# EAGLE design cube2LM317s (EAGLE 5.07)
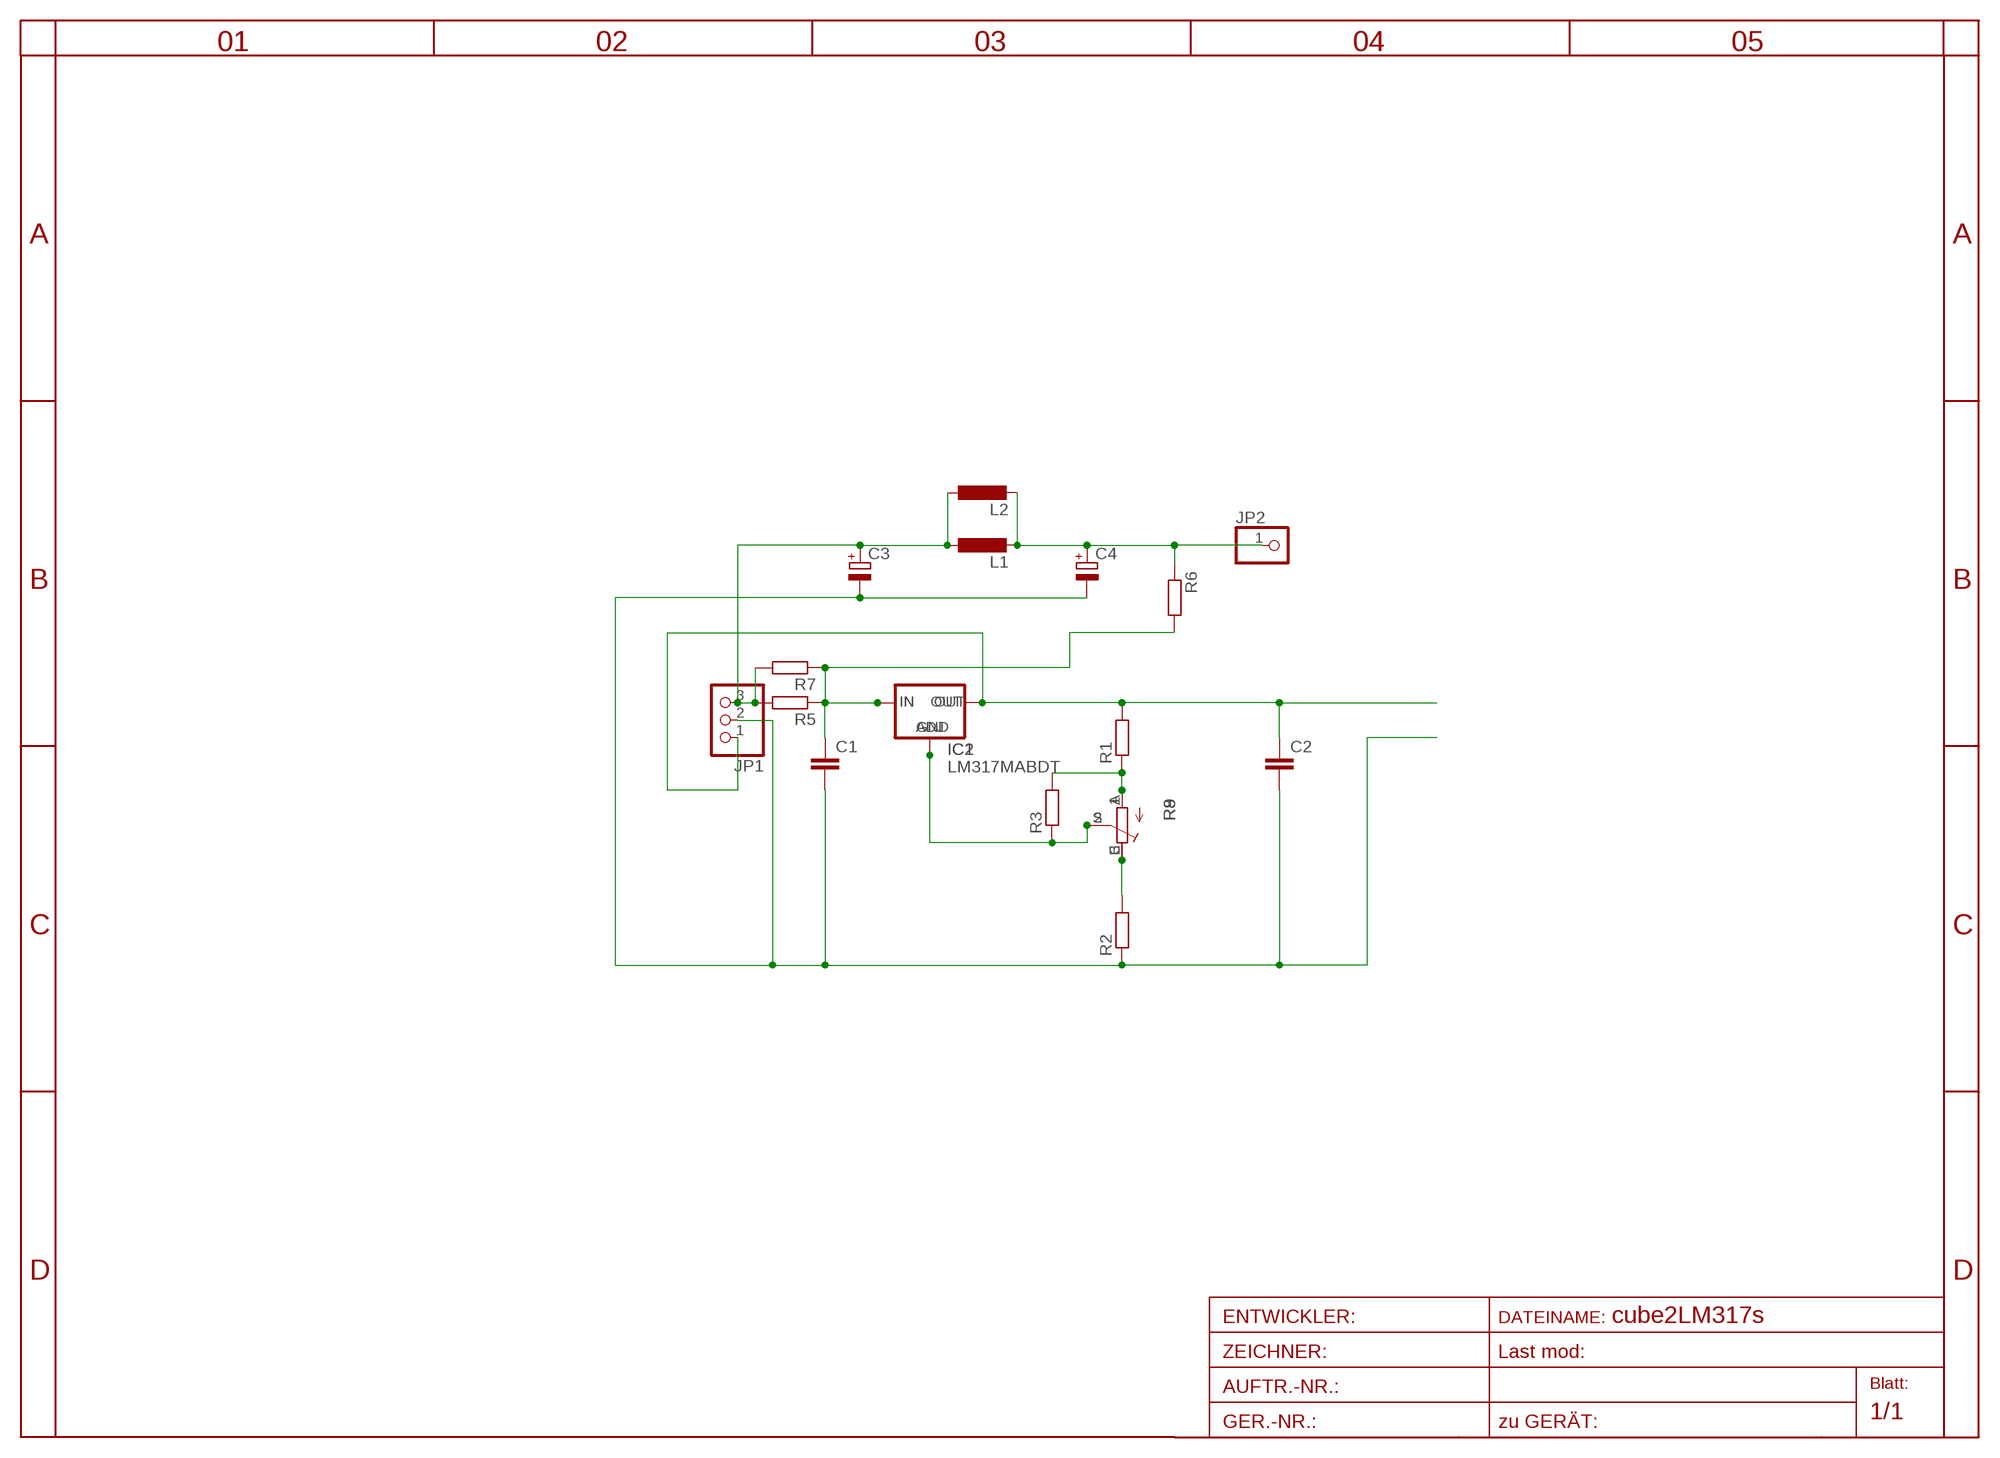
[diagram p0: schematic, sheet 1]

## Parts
C1  C-EUC1206  [C1206]
C2  C-EUC1206  [C1206]
C3  CPOL-EUE  [PANASONIC_E]
C4  CPOL-EUE  [PANASONIC_E]
IC1  LM317MABDT  [DPACK]
IC2  78XXS  [78XXS]
JP1  PINHD-1X3  [1X03]
JP2  PINHD-1X11X0.4  [1X01]
L1  L-EUPIS2816  [PIS2816]
L2  L-EUOPEN  [OPEN5]
R1  R-EU_R0805  [R0805]
R2  R-EU_R1206  [R1206]
R3  R-EU_R0805  [R0805]
R5  R-EU_R0805  [R0805]
R6  R-EU_R0805  [R0805]
R7  R-EU_R0805  [R0805]
R8  TRIM_EU-RAND160  [RANDL]
R9  R-TRIMM3214W  [RTRIM3214W]

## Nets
GND: C1.2 C2.2 C3.- C4.- JP1.2 R2.1
IN: C1.1 IC1.3(IN) IC2.IN R5.1 R6.2 R7.1
N$1: C3.+ JP1.3 L1.1 L2.1 R5.2 R7.2
N$3: C4.+ JP2.1 L1.2 L2.2 R6.1
N$4: IC1.1(ADJ) IC2.GND R3.1 R8.S R9.2(S)
N$6: R2.2 R8.E R9.3(A)
N$7: R1.1 R3.2 R8.A R9.1(E)
OUT: C2.1 IC1.4(OUT) IC2.OUT JP1.1 R1.2

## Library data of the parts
C1 C2 = rcl:C-EU: CAPACITOR, European symbol
C3 C4 = rcl:CPOL-EU: POLARIZED CAPACITOR, European symbol
IC1 = v-reg:LM317?*: 500 mA Adjustable Output Positive Voltage Regulator Source: http://www.onsemi.co.jp .. LM317M-D.PDF
IC2 = v-reg:78XXS: VOLTAGE REGULATOR
JP1 = pinhead:PINHD-1X3: PIN HEADER
JP2 = pinhead:PINHD-1X1: PIN HEADER
L1 L2 = rcl:L-EU: INDUCTOR, European symbol
R1-R3 R5-R7 = rcl:R-EU_: RESISTOR, European symbol
R8 = pot:TRIM_EU-: POTENTIOMETER
R9 = rcl:R-TRIMM: Trimm resistor

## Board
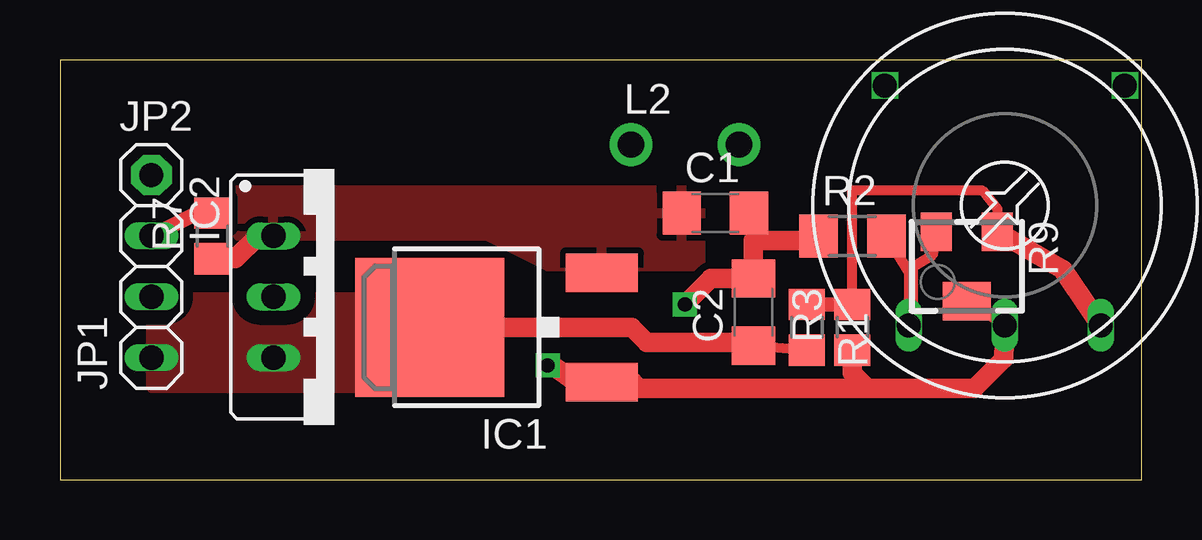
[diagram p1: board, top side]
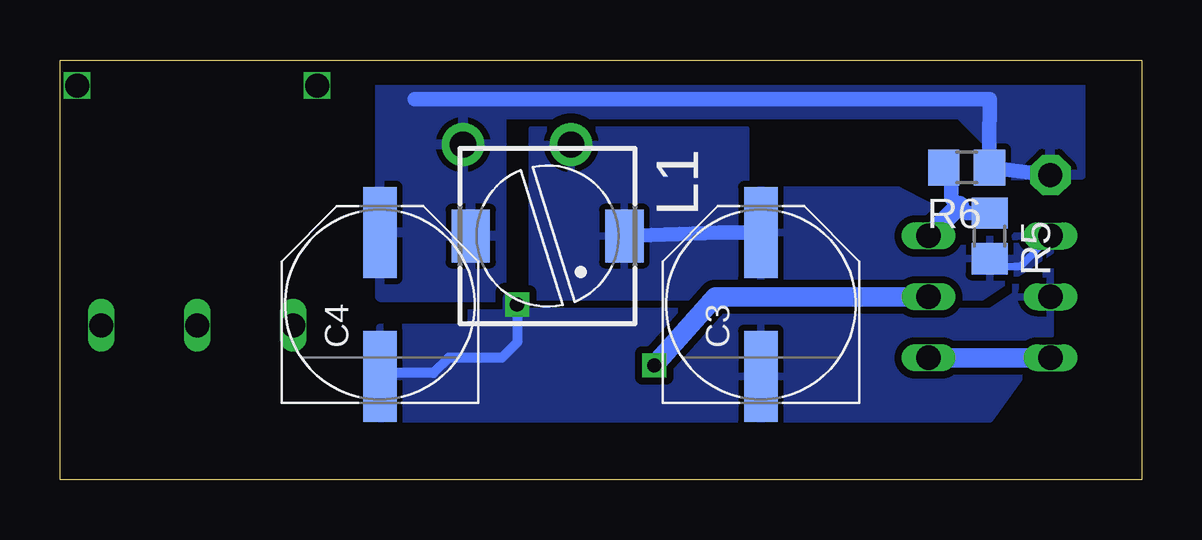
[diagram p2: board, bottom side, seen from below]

Size 45.08 x 17.5 mm. Coordinates in mm from the lower left corner, seen from the top.
Outline: 0,0 45.08,0 45.08,17.5 0,17.5 0,0
Copper layers (1*16): Top 0.035mm / dielectric 1.5mm / Bottom 0.035mm
Design rules "default": minimum track width 10mil, minimum drill 20mil, track to track 8mil, track to pad 8mil, pad to pad 8mil, via to via 8mil, smd to smd 8mil, copper to edge 40mil, drill to drill 8mil, minimum pad ring 1mil, minimum via ring 8mil, stop-mask expansion 4mil, vias tented up to drill 0mil, thermal gap 10mil

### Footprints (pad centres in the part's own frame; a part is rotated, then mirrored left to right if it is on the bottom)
C1206 = smd 1.6 x 1.8: 1 -1.4,0; 2 1.4,0
PANASONIC_E = smd 3.8 x 1.4: + 3,0; - -3,0
DPACK = smd 1.6 x 3: 1 -2.28,-4.8; 3 2.28,-4.8 | smd 5.8 x 6.2: 4 0,2.38
78XXS = drill 1.016 long: GND 0,-2.54; IN -2.54,-2.54; OUT 2.54,-2.54
1X03 = drill 1.016 long: 1 -2.54,0; 2 0,0; 3 2.54,0
1X01 = drill 1 pad 1.676 octagon: 1 0,0
PIS2816 = smd 2.2 x 1.6: 1 0,3.2; 2 0,-3.2
OPEN5 = drill 1.1 pad 1.778 round: 1 -2.25,0; 2 2.25,0
R0805 = smd 1.3 x 1.5: 1 -0.95,0; 2 0.95,0
R1206 = smd 1.6 x 1.803: 1 -1.422,0; 2 1.422,0
RANDL = drill 1 long: A -4,5; E 4,5; S 0,5 | drill 1 square: P$1 -5,-5; P$2 5,-5
RTRIM3214W = smd 1.3 x 1.6: 1 -1.275,-1.45; 3 1.275,-1.45 | smd 2 x 1.6: 2 0,1.45

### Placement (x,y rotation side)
C1  27.3,11.11 0 top
C2  28.89,6.99 90 top
C3  15.88,7.3 90 bottom
C4  31.75,7.3 90 bottom
IC1  17.78,6.35 90 top
IC2  11.43,7.62 270 top
JP1  3.81,7.62 90 top
JP2  3.81,12.7 0 top
L1  24.77,10.16 270 bottom
L2  26.04,13.97 0 top
R1  31.11,6.35 270 top
R2  33.02,10.16 0 top
R3  33.02,6.35 90 top
R5  6.35,10.16 270 bottom
R6  7.3,13.02 180 bottom
R7  6.35,10.16 90 top
R8  39.37,11.43 180 top
R9  37.78,8.89 180 top

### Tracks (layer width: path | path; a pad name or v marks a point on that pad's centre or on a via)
GND  (via drill 0.6)
  Top 0.406: 31.6,10.01 R2.1 31.41,9.97 | 28.89,9.97 C1.2
  Top 0.813: v26.04,7.3 27.12,8.38 C2.2 28.89,9.97 31.41,9.97
  Bottom 0.406: v26.04,7.3 26.04,5.71 26.67,5.08 28.89,5.08 29.53,4.45 31.61,4.45 C4.-
  pour Bottom (isolate 0.305, rank 3): 3.81,6.03 3.81,8.89 6.35,7.62 27.94,7.62 27.94,6.35 31.75,6.35 31.75,2.54 6.35,2.54
IN
  Top 0.813: R7.1 7.3,9.21 8.26,10.16 IC2.IN
  Bottom 0.61: R5.1 7.3,11.11 7.62,11.43 7.94,11.75 7.94,12.7 R6.2
  Bottom 0.813: IC2.IN 7.62,11.43
  pour Top (isolate 0.305): 26.67,12.06 26.67,8.89 20.32,8.89 17.78,10.16 6.35,10.16 6.35,12.06
N$1
  Top 0.61: R7.2 6.35,11.43 JP1.3
  Bottom 0.305: JP1.3 5.08,8.89 6.03,8.89 R5.2
  Bottom 0.61: C3.+ 17.61,10.3 L1.1
  pour Bottom (isolate 0.305, rank 2): 2.86,10.16 6.67,7.62 25.4,7.62 25.4,14.61 16.51,14.61 16.51,12.06 10.16,12.06 8.89,11.43
N$3
  Bottom 0.61: 30.3,15.88 6.35,15.88 6.35,13.97 R6.1 JP2.1
  pour Bottom (isolate 0.406): 2.54,16.51 31.75,16.51 31.75,7.62 26.67,7.62 26.67,15.24 7.62,15.24 6.35,13.97 6.35,12.7 2.54,12.7
N$4  (via drill 0.6)
  Top 0.406: 21.58,4.01 IC1.1 | R8.S R9.2
  Top 0.813: R3.1 33.02,4.45 33.66,3.81 | R8.S 39.33,5.04 38.1,3.81 33.66,3.81 | v20.32,4.76 20.51,4.76 21.58,4.01 | IC1.1 23.87,4.07 24.13,3.81 33.66,3.81
  Bottom 0.813: IC2.GND 17.78,7.62 v20.32,4.76
N$6
  Top 0.406: R9.3 36.38,9.39 35.56,8.89 35.56,6.62 R8.E 35.4,8.63 R2.2
N$7
  Top 0.406: R3.2 33.02,12.06 38.42,12.06 39.05,11.29 R9.1
  Top 0.61: R1.1 R3.2
  Top 0.813: R9.1 41.77,8.75 R8.A
OUT
  Top 0.406: 28.76,5.71 C2.1 R1.2
  Top 0.813: IC1.4 23.81,6.35 24.45,5.71 28.76,5.71
  Bottom 0.813: JP1.1 IC2.OUT
  pour Top (isolate 0.61, no thermals): 3.81,7.62 16.51,7.62 16.51,3.81 3.81,3.81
